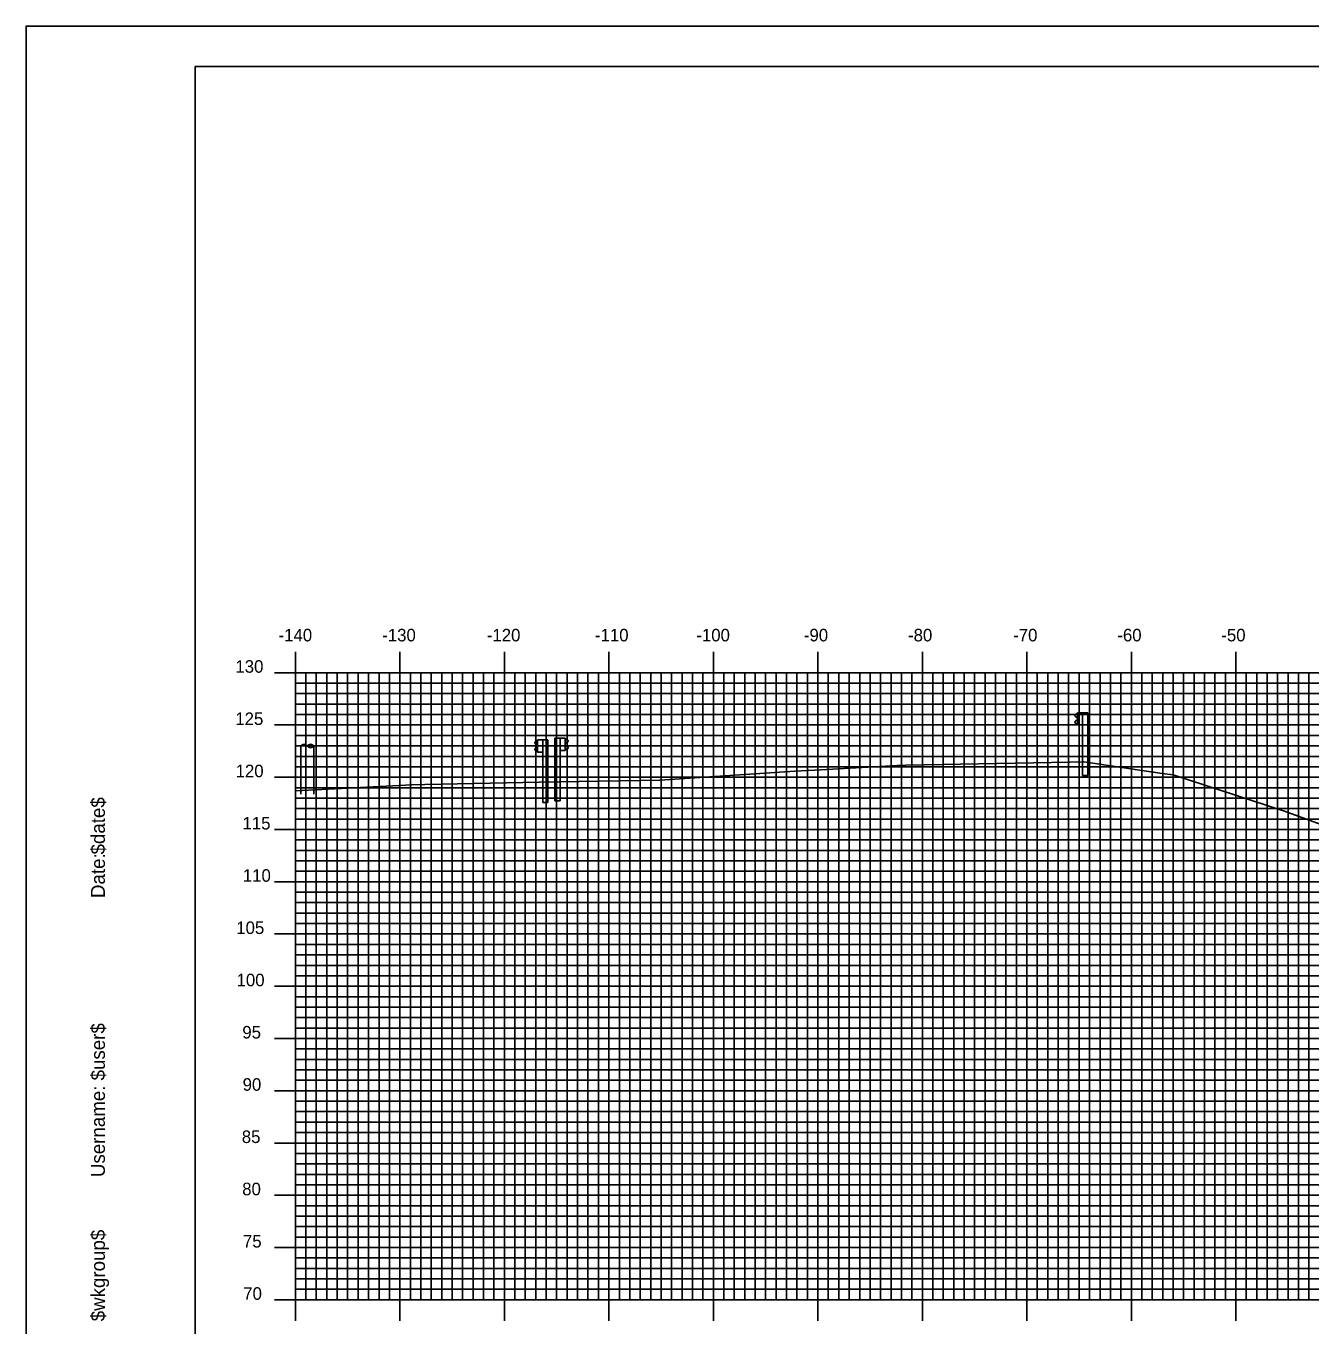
# Model space of a CAD drawing. Extents: x 858291 to 858634, y 364765 to 364985.
# Drawn here: x 858290.5 to 858413.4, y 364860.8 to 364985.2 of the extents above; entities that cross this region are included whole.
import ezdxf

# ---------------------------------------------------------------- set-up
doc = ezdxf.new("R2010")
doc.units = 0
for name, color, linetype in [('BORDER', 7, 'Continuous'), ('H_V ANNOTATION', 7, 'Continuous'), ('M_Guardrail', 7, 'Continuous'), ('M_Roadway_Centerline', 7, 'Continuous'), ('M_Utilities_Pole_StreetLight', 7, 'Continuous'), ('MAJOR', 7, 'Continuous'), ('MINOR', 7, 'Continuous'), ('PLOT BOUNDARY', 7, 'Continuous'), ('S_Roadway_Centerline', 7, 'Continuous')]:
    doc.layers.add(name, color=color, linetype=linetype)

msp = doc.modelspace()

# ---------------------------------------------------------------- linework, layer by layer
at = {"layer": 'BORDER'}
msp.add_lwpolyline([(858306.73, 364771.3), (858626.73, 364771.3), (858626.73, 364981.3), (858306.73, 364981.3)], close=True, dxfattribs=at)
at = {"layer": 'M_Guardrail'}
for p, q in [((858391.09, 364919.38), (858390.94, 364919.28)), ((858390.94, 364919.14), (858391.14, 364919)), ((858391.14, 364918.78), (858390.94, 364918.65)), ((858391.18, 364919.4), (858391.1, 364919.39)), ((858391.17, 364918.94), (858391.17, 364918.85)), ((858391.18, 364919.47), (858391.67, 364919.47)), ((858391.18, 364918.31), (858391.18, 364919.47)), ((858391.67, 364919.47), (858392.17, 364919.47)), ((858391.67, 364919.47), (858391.67, 364918.31)), ((858392.17, 364919.47), (858392.17, 364913.47)), ((858390.94, 364918.5), (858391.09, 364918.4)), ((858391.1, 364918.4), (858391.18, 364918.38)), ((858391.67, 364918.31), (858391.18, 364918.31)), ((858391.67, 364913.47), (858391.67, 364918.31)), ((858339.42, 364916.78), (858339.27, 364916.68)), ((858339.27, 364916.53), (858339.47, 364916.4)), ((858339.51, 364916.8), (858339.43, 364916.78)), ((858339.5, 364916.33), (858339.5, 364916.24)), ((858339.51, 364916.87), (858340, 364916.87)), ((858339.51, 364915.7), (858339.51, 364916.87)), ((858340, 364916.87), (858340.5, 364916.87)), ((858340, 364916.87), (858340, 364915.7)), ((858340.5, 364916.87), (858340.5, 364910.87)), ((858341.17, 364917.03), (858341.17, 364911.03)), ((858341.66, 364917.03), (858341.17, 364917.03)), ((858342.15, 364917.03), (858341.66, 364917.03)), ((858341.66, 364917.03), (858341.66, 364915.86)), ((858342.15, 364915.86), (858342.15, 364917.03)), ((858342.15, 364916.96), (858342.23, 364916.94)), ((858342.16, 364916.49), (858342.16, 364916.4)), ((858342.39, 364916.69), (858342.19, 364916.56)), ((858342.19, 364916.34), (858342.39, 364916.2)), ((858342.25, 364916.93), (858342.39, 364916.83)), ((858339.47, 364916.18), (858339.27, 364916.04)), ((858339.27, 364915.9), (858339.42, 364915.8)), ((858339.43, 364915.79), (858339.51, 364915.78)), ((858340, 364915.7), (858339.51, 364915.7)), ((858340, 364910.87), (858340, 364915.7)), ((858341.66, 364911.03), (858341.66, 364915.86)), ((858341.66, 364915.86), (858342.15, 364915.86)), ((858342.23, 364915.95), (858342.15, 364915.93)), ((858342.39, 364916.06), (858342.25, 364915.96)), ((858391.67, 364913.47), (858392.17, 364913.47)), ((858340, 364910.87), (858340.5, 364910.87)), ((858341.66, 364911.03), (858341.17, 364911.03))]:
    msp.add_line(p, q, dxfattribs=at)
for centre, major_axis, start_param, end_param in [((858390.99, 364919.21), (-0.0877, 0), 5.323254, 7.243116), ((858391.11, 364919.35), (-0.0417, 0), 4.886922, 5.323254), ((858391.09, 364918.94), (0.0789, 0), 0, 0.959931), ((858391.09, 364918.85), (0.0789, 0), 5.323254, 6.283185), ((858390.99, 364918.57), (-0.0877, 0), 5.323254, 7.243116), ((858391.11, 364918.44), (-0.0417, 0), 0.959931, 1.396263), ((858339.32, 364916.61), (-0.0877, 0), 5.323254, 7.243116), ((858339.44, 364916.74), (-0.0417, 0), 4.886922, 5.323254), ((858339.42, 364916.33), (0.0789, 0), 0, 0.959931), ((858342.24, 364916.49), (-0.0789, 0), 5.323254, 6.283185), ((858342.24, 364916.4), (-0.0789, 0), 6.283185, 7.243116), ((858342.22, 364916.9), (0.0417, 0), 0.959931, 1.396263), ((858342.34, 364916.76), (0.0877, 0), 5.323254, 7.243116), ((858339.32, 364915.97), (-0.0877, 0), 5.323254, 7.243116), ((858339.44, 364915.83), (-0.0417, 0), 0.959931, 1.396263), ((858339.42, 364916.24), (0.0789, 0), 5.323254, 6.283185), ((858342.22, 364915.99), (0.0417, 0), 4.886922, 5.323254), ((858342.34, 364916.13), (0.0877, 0), 5.323254, 7.243116)]:
    msp.add_ellipse(centre, major_axis=major_axis, ratio=0.995501, start_param=start_param, end_param=end_param, dxfattribs=at)
at = {"layer": 'M_Utilities_Pole_StreetLight'}
for p, q in [((858316.84, 364916.29), (858317, 364916.4)), ((858316.84, 364911.67), (858316.84, 364916.29)), ((858317.31, 364916.4), (858317.47, 364916.29)), ((858317.62, 364916.4), (858317.47, 364916.29)), ((858317.47, 364916.29), (858317.62, 364916.18)), ((858318.09, 364916.29), (858317.94, 364916.4)), ((858317.94, 364916.18), (858318.09, 364916.29)), ((858318.09, 364911.67), (858318.09, 364916.29))]:
    msp.add_line(p, q, dxfattribs=at)
for centre, start, end in [((858317.15, 364916.18), 90, 125.2644), ((858317.15, 364916.18), 54.7356, 90), ((858317.78, 364916.18), 90, 125.2644), ((858317.78, 364916.18), 54.7356, 90), ((858317.78, 364916.4), 234.7356, 270), ((858317.78, 364916.4), 270, 305.2644)]:
    msp.add_arc(centre, 0.271, start, end, dxfattribs=at)
at = {"layer": 'MAJOR'}
for p, q in [((858316.33, 364925.31), (858316.33, 364923.3)), ((858326.33, 364925.31), (858326.33, 364923.3)), ((858336.33, 364925.31), (858336.33, 364923.3)), ((858346.33, 364925.31), (858346.33, 364923.3)), ((858356.33, 364925.31), (858356.33, 364923.3)), ((858366.33, 364925.31), (858366.33, 364923.3)), ((858376.33, 364925.31), (858376.33, 364923.3)), ((858386.33, 364925.31), (858386.33, 364923.3)), ((858396.33, 364925.31), (858396.33, 364923.3)), ((858406.33, 364925.31), (858406.33, 364923.3)), ((858314.33, 364923.3), (858316.33, 364923.3)), ((858316.33, 364923.3), (858596.33, 364923.3)), ((858316.33, 364863.3), (858316.33, 364923.3)), ((858316.33, 364863.3), (858316.33, 364923.3)), ((858316.33, 364923.3), (858596.33, 364923.3)), ((858326.33, 364863.3), (858326.33, 364923.3)), ((858336.33, 364863.3), (858336.33, 364923.3)), ((858346.33, 364863.3), (858346.33, 364923.3)), ((858356.33, 364863.3), (858356.33, 364923.3)), ((858366.33, 364863.3), (858366.33, 364923.3)), ((858376.33, 364863.3), (858376.33, 364923.3)), ((858386.33, 364863.3), (858386.33, 364923.3)), ((858396.33, 364863.3), (858396.33, 364923.3)), ((858406.33, 364863.3), (858406.33, 364923.3)), ((858314.33, 364918.3), (858316.33, 364918.3)), ((858316.33, 364918.3), (858596.33, 364918.3)), ((858314.33, 364913.3), (858316.33, 364913.3)), ((858316.33, 364913.3), (858596.33, 364913.3)), ((858314.33, 364908.3), (858316.33, 364908.3)), ((858316.33, 364908.3), (858596.33, 364908.3)), ((858314.33, 364903.3), (858316.33, 364903.3)), ((858316.33, 364903.3), (858596.33, 364903.3)), ((858314.33, 364898.3), (858316.33, 364898.3)), ((858316.33, 364898.3), (858596.33, 364898.3)), ((858314.33, 364893.3), (858316.33, 364893.3)), ((858316.33, 364893.3), (858596.33, 364893.3)), ((858314.33, 364888.3), (858316.33, 364888.3)), ((858316.33, 364888.3), (858596.33, 364888.3)), ((858314.33, 364883.3), (858316.33, 364883.3)), ((858316.33, 364883.3), (858596.33, 364883.3)), ((858314.33, 364878.3), (858316.33, 364878.3)), ((858316.33, 364878.3), (858596.33, 364878.3)), ((858314.33, 364873.3), (858316.33, 364873.3)), ((858316.33, 364873.3), (858596.33, 364873.3)), ((858314.33, 364868.3), (858316.33, 364868.3)), ((858316.33, 364868.3), (858596.33, 364868.3)), ((858314.33, 364863.3), (858316.33, 364863.3)), ((858316.33, 364863.3), (858596.33, 364863.3)), ((858316.33, 364863.3), (858596.33, 364863.3)), ((858316.33, 364861.3), (858316.33, 364863.3)), ((858326.33, 364861.3), (858326.33, 364863.3)), ((858336.33, 364861.3), (858336.33, 364863.3)), ((858346.33, 364861.3), (858346.33, 364863.3)), ((858356.33, 364861.3), (858356.33, 364863.3)), ((858366.33, 364861.3), (858366.33, 364863.3)), ((858376.33, 364861.3), (858376.33, 364863.3)), ((858386.33, 364861.3), (858386.33, 364863.3)), ((858396.33, 364861.3), (858396.33, 364863.3)), ((858406.33, 364861.3), (858406.33, 364863.3))]:
    msp.add_line(p, q, dxfattribs=at)
at = {"layer": 'MINOR'}
for p, q in [((858317.33, 364863.3), (858317.33, 364923.3)), ((858318.33, 364863.3), (858318.33, 364923.3)), ((858319.33, 364863.3), (858319.33, 364923.3)), ((858320.33, 364863.3), (858320.33, 364923.3)), ((858321.33, 364863.3), (858321.33, 364923.3)), ((858322.33, 364863.3), (858322.33, 364923.3)), ((858323.33, 364863.3), (858323.33, 364923.3)), ((858324.33, 364863.3), (858324.33, 364923.3)), ((858325.33, 364863.3), (858325.33, 364923.3)), ((858327.33, 364863.3), (858327.33, 364923.3)), ((858328.33, 364863.3), (858328.33, 364923.3)), ((858329.33, 364863.3), (858329.33, 364923.3)), ((858330.33, 364863.3), (858330.33, 364923.3)), ((858331.33, 364863.3), (858331.33, 364923.3)), ((858332.33, 364863.3), (858332.33, 364923.3)), ((858333.33, 364863.3), (858333.33, 364923.3)), ((858334.33, 364863.3), (858334.33, 364923.3)), ((858335.33, 364863.3), (858335.33, 364923.3)), ((858337.33, 364863.3), (858337.33, 364923.3)), ((858338.33, 364863.3), (858338.33, 364923.3)), ((858339.33, 364863.3), (858339.33, 364923.3)), ((858340.33, 364863.3), (858340.33, 364923.3)), ((858341.33, 364863.3), (858341.33, 364923.3)), ((858342.33, 364863.3), (858342.33, 364923.3)), ((858343.33, 364863.3), (858343.33, 364923.3)), ((858344.33, 364863.3), (858344.33, 364923.3)), ((858345.33, 364863.3), (858345.33, 364923.3)), ((858347.33, 364863.3), (858347.33, 364923.3)), ((858348.33, 364863.3), (858348.33, 364923.3)), ((858349.33, 364863.3), (858349.33, 364923.3)), ((858350.33, 364863.3), (858350.33, 364923.3)), ((858351.33, 364863.3), (858351.33, 364923.3)), ((858352.33, 364863.3), (858352.33, 364923.3)), ((858353.33, 364863.3), (858353.33, 364923.3)), ((858354.33, 364863.3), (858354.33, 364923.3)), ((858355.33, 364863.3), (858355.33, 364923.3)), ((858357.33, 364863.3), (858357.33, 364923.3)), ((858358.33, 364863.3), (858358.33, 364923.3)), ((858359.33, 364863.3), (858359.33, 364923.3)), ((858360.33, 364863.3), (858360.33, 364923.3)), ((858361.33, 364863.3), (858361.33, 364923.3)), ((858362.33, 364863.3), (858362.33, 364923.3)), ((858363.33, 364863.3), (858363.33, 364923.3)), ((858364.33, 364863.3), (858364.33, 364923.3)), ((858365.33, 364863.3), (858365.33, 364923.3)), ((858367.33, 364863.3), (858367.33, 364923.3)), ((858368.33, 364863.3), (858368.33, 364923.3)), ((858369.33, 364863.3), (858369.33, 364923.3)), ((858370.33, 364863.3), (858370.33, 364923.3)), ((858371.33, 364863.3), (858371.33, 364923.3)), ((858372.33, 364863.3), (858372.33, 364923.3)), ((858373.33, 364863.3), (858373.33, 364923.3)), ((858374.33, 364863.3), (858374.33, 364923.3)), ((858375.33, 364863.3), (858375.33, 364923.3)), ((858377.33, 364863.3), (858377.33, 364923.3)), ((858378.33, 364863.3), (858378.33, 364923.3)), ((858379.33, 364863.3), (858379.33, 364923.3)), ((858380.33, 364863.3), (858380.33, 364923.3)), ((858381.33, 364863.3), (858381.33, 364923.3)), ((858382.33, 364863.3), (858382.33, 364923.3)), ((858383.33, 364863.3), (858383.33, 364923.3)), ((858384.33, 364863.3), (858384.33, 364923.3)), ((858385.33, 364863.3), (858385.33, 364923.3)), ((858387.33, 364863.3), (858387.33, 364923.3)), ((858388.33, 364863.3), (858388.33, 364923.3)), ((858389.33, 364863.3), (858389.33, 364923.3)), ((858390.33, 364863.3), (858390.33, 364923.3)), ((858391.33, 364863.3), (858391.33, 364923.3)), ((858392.33, 364863.3), (858392.33, 364923.3)), ((858393.33, 364863.3), (858393.33, 364923.3)), ((858394.33, 364863.3), (858394.33, 364923.3)), ((858395.33, 364863.3), (858395.33, 364923.3)), ((858397.33, 364863.3), (858397.33, 364923.3)), ((858398.33, 364863.3), (858398.33, 364923.3)), ((858399.33, 364863.3), (858399.33, 364923.3)), ((858400.33, 364863.3), (858400.33, 364923.3)), ((858401.33, 364863.3), (858401.33, 364923.3)), ((858402.33, 364863.3), (858402.33, 364923.3)), ((858403.33, 364863.3), (858403.33, 364923.3)), ((858404.33, 364863.3), (858404.33, 364923.3)), ((858405.33, 364863.3), (858405.33, 364923.3)), ((858407.33, 364863.3), (858407.33, 364923.3)), ((858408.33, 364863.3), (858408.33, 364923.3)), ((858409.33, 364863.3), (858409.33, 364923.3)), ((858410.33, 364863.3), (858410.33, 364923.3)), ((858411.33, 364863.3), (858411.33, 364923.3)), ((858412.33, 364863.3), (858412.33, 364923.3)), ((858413.33, 364863.3), (858413.33, 364923.3)), ((858316.33, 364922.3), (858596.33, 364922.3)), ((858316.33, 364922.3), (858318.34, 364922.3)), ((858316.33, 364921.3), (858596.33, 364921.3)), ((858316.33, 364921.3), (858318.34, 364921.3)), ((858316.33, 364920.3), (858596.33, 364920.3)), ((858316.33, 364920.3), (858318.34, 364920.3)), ((858316.33, 364919.3), (858596.33, 364919.3)), ((858316.33, 364919.3), (858318.34, 364919.3)), ((858316.33, 364917.3), (858596.33, 364917.3)), ((858316.33, 364917.3), (858318.34, 364917.3)), ((858316.33, 364916.3), (858596.33, 364916.3)), ((858316.33, 364916.3), (858318.34, 364916.3)), ((858316.33, 364915.3), (858596.33, 364915.3)), ((858316.33, 364915.3), (858318.34, 364915.3)), ((858316.33, 364914.3), (858596.33, 364914.3)), ((858316.33, 364914.3), (858318.34, 364914.3)), ((858316.33, 364912.3), (858596.33, 364912.3)), ((858316.33, 364912.3), (858318.34, 364912.3)), ((858316.33, 364911.3), (858596.33, 364911.3)), ((858316.33, 364911.3), (858318.34, 364911.3)), ((858316.33, 364910.3), (858596.33, 364910.3)), ((858316.33, 364910.3), (858318.34, 364910.3)), ((858316.33, 364909.3), (858596.33, 364909.3)), ((858316.33, 364909.3), (858318.34, 364909.3)), ((858316.33, 364907.3), (858596.33, 364907.3)), ((858316.33, 364907.3), (858318.34, 364907.3)), ((858316.33, 364906.3), (858596.33, 364906.3)), ((858316.33, 364906.3), (858318.34, 364906.3)), ((858316.33, 364905.3), (858596.33, 364905.3)), ((858316.33, 364905.3), (858318.34, 364905.3)), ((858316.33, 364904.3), (858596.33, 364904.3)), ((858316.33, 364904.3), (858318.34, 364904.3)), ((858316.33, 364902.3), (858596.33, 364902.3)), ((858316.33, 364902.3), (858318.34, 364902.3)), ((858316.33, 364901.3), (858596.33, 364901.3)), ((858316.33, 364901.3), (858318.34, 364901.3)), ((858316.33, 364900.3), (858596.33, 364900.3)), ((858316.33, 364900.3), (858318.34, 364900.3)), ((858316.33, 364899.3), (858596.33, 364899.3)), ((858316.33, 364899.3), (858318.34, 364899.3)), ((858316.33, 364897.3), (858596.33, 364897.3)), ((858316.33, 364897.3), (858318.34, 364897.3)), ((858316.33, 364896.3), (858596.33, 364896.3)), ((858316.33, 364896.3), (858318.34, 364896.3)), ((858316.33, 364895.3), (858596.33, 364895.3)), ((858316.33, 364895.3), (858318.34, 364895.3)), ((858316.33, 364894.3), (858596.33, 364894.3)), ((858316.33, 364894.3), (858318.34, 364894.3)), ((858316.33, 364892.3), (858596.33, 364892.3)), ((858316.33, 364892.3), (858318.34, 364892.3)), ((858316.33, 364891.3), (858596.33, 364891.3)), ((858316.33, 364891.3), (858318.34, 364891.3)), ((858316.33, 364890.3), (858596.33, 364890.3)), ((858316.33, 364890.3), (858318.34, 364890.3)), ((858316.33, 364889.3), (858596.33, 364889.3)), ((858316.33, 364889.3), (858318.34, 364889.3)), ((858316.33, 364887.3), (858596.33, 364887.3)), ((858316.33, 364887.3), (858318.34, 364887.3)), ((858316.33, 364886.3), (858596.33, 364886.3)), ((858316.33, 364886.3), (858318.34, 364886.3)), ((858316.33, 364885.3), (858596.33, 364885.3)), ((858316.33, 364885.3), (858318.34, 364885.3)), ((858316.33, 364884.3), (858596.33, 364884.3)), ((858316.33, 364884.3), (858318.34, 364884.3)), ((858316.33, 364882.3), (858596.33, 364882.3)), ((858316.33, 364882.3), (858318.34, 364882.3)), ((858316.33, 364881.3), (858596.33, 364881.3)), ((858316.33, 364881.3), (858318.34, 364881.3)), ((858316.33, 364880.3), (858596.33, 364880.3)), ((858316.33, 364880.3), (858318.34, 364880.3)), ((858316.33, 364879.3), (858596.33, 364879.3)), ((858316.33, 364879.3), (858318.34, 364879.3)), ((858316.33, 364877.3), (858596.33, 364877.3)), ((858316.33, 364877.3), (858318.34, 364877.3)), ((858316.33, 364876.3), (858596.33, 364876.3)), ((858316.33, 364876.3), (858318.34, 364876.3)), ((858316.33, 364875.3), (858596.33, 364875.3)), ((858316.33, 364875.3), (858318.34, 364875.3)), ((858316.33, 364874.3), (858596.33, 364874.3)), ((858316.33, 364874.3), (858318.34, 364874.3)), ((858316.33, 364872.3), (858596.33, 364872.3)), ((858316.33, 364872.3), (858318.34, 364872.3)), ((858316.33, 364871.3), (858596.33, 364871.3)), ((858316.33, 364871.3), (858318.34, 364871.3)), ((858316.33, 364870.3), (858596.33, 364870.3)), ((858316.33, 364870.3), (858318.34, 364870.3)), ((858316.33, 364869.3), (858596.33, 364869.3)), ((858316.33, 364869.3), (858318.34, 364869.3)), ((858316.33, 364867.3), (858596.33, 364867.3)), ((858316.33, 364867.3), (858318.34, 364867.3)), ((858316.33, 364866.3), (858596.33, 364866.3)), ((858316.33, 364866.3), (858318.34, 364866.3)), ((858316.33, 364865.3), (858596.33, 364865.3)), ((858316.33, 364865.3), (858318.34, 364865.3)), ((858316.33, 364864.3), (858596.33, 364864.3)), ((858316.33, 364864.3), (858318.34, 364864.3))]:
    msp.add_line(p, q, dxfattribs=at)
at = {"layer": 'PLOT BOUNDARY'}
msp.add_lwpolyline([(858290.55, 364765.18), (858630.55, 364765.18), (858630.55, 364985.18), (858290.55, 364985.18)], close=True, dxfattribs=at)
at = {"layer": 'S_Roadway_Centerline'}
msp.add_lwpolyline([(858316.33, 364911.99), (858318.85, 364912.12), (858327.46, 364912.56), (858328.72, 364912.59), (858339.66, 364912.82), (858351.17, 364913.02), (858351.21, 364913.03), (858364.11, 364913.89), (858366.04, 364913.99), (858373.93, 364914.41), (858374.03, 364914.42), (858374.74, 364914.46), (858390.45, 364914.75), (858391.72, 364914.78), (858391.73, 364914.77), (858391.79, 364914.77), (858399.27, 364913.66), (858400.33, 364913.52), (858410.89, 364910.1), (858424.16, 364905.26)], dxfattribs=at)

# ---------------------------------------------------------------- texts
at = {"layer": 'BORDER'}
for s, p in [('$date$', (858298.1, 364905.91)), ('Date:', (858298.1, 364901.74)), ('$user$', (858298.1, 364884.29)), ('Username:', (858298.1, 364875.04)), ('$wkgroup$', (858298.1, 364861.24))]:
    msp.add_text(s, height=1.339, rotation=90, dxfattribs=at).set_placement(p)
at = {"layer": 'H_V ANNOTATION'}
for s, p in [('-140', (858314.72, 364926.3)), ('-130', (858324.64, 364926.3)), ('-120', (858334.65, 364926.3)), ('-110', (858345, 364926.3)), ('-100', (858354.7, 364926.3)), ('-90', (858364.99, 364926.3)), ('-80', (858374.96, 364926.3)), ('-70', (858385.02, 364926.3)), ('-60', (858394.99, 364926.3)), ('-50', (858404.94, 364926.3)), ('130', (858310.59, 364923.3)), ('125', (858310.58, 364918.3)), ('120', (858310.61, 364913.3)), ('115', (858311.27, 364908.3)), ('110', (858311.3, 364903.3)), ('105', (858310.67, 364898.3)), ('100', (858310.7, 364893.3)), ('95', (858311.25, 364888.3)), ('90', (858311.28, 364883.3)), ('85', (858311.2, 364878.3)), ('80', (858311.24, 364873.3)), ('75', (858311.31, 364868.3)), ('70', (858311.34, 364863.3))]:
    msp.add_text(s, height=1.2, dxfattribs=at).set_placement(p)
at = {"layer": 'M_Roadway_Centerline'}
for s, p in [('C', (858364.1, 364913.89)), ('L', (858364.11, 364913.89))]:
    msp.add_text(s, height=0.0146, dxfattribs=at).set_placement(p)
at = {"layer": 'MAJOR'}
msp.add_text('-', height=0.012, dxfattribs=at).set_placement((858316.32, 364863.3))

doc.saveas('drawing.dxf')
